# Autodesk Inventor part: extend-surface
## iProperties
Shininess: 64.0
Length Units: 11269
Angle Units: 11279
Time Units: 11290
Mass Units: 11283
Length Display Precision: 3
Angle Display Precision: 2
Compacted: True
Part Number: extend-surface
Document SubType Name: Modeling
Created: 2003-08
Designer: Owner
Manufacturer: Standard
Standards Organization: Custom
Density: 0.0
Volumn: 0.0
Area: 0.0
PropertySet Name: Model Information
Control State: 0
Master: False
Checked Out: False
Author: Owner
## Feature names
1. Split6
